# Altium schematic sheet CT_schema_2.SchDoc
size 271 x 273 mm
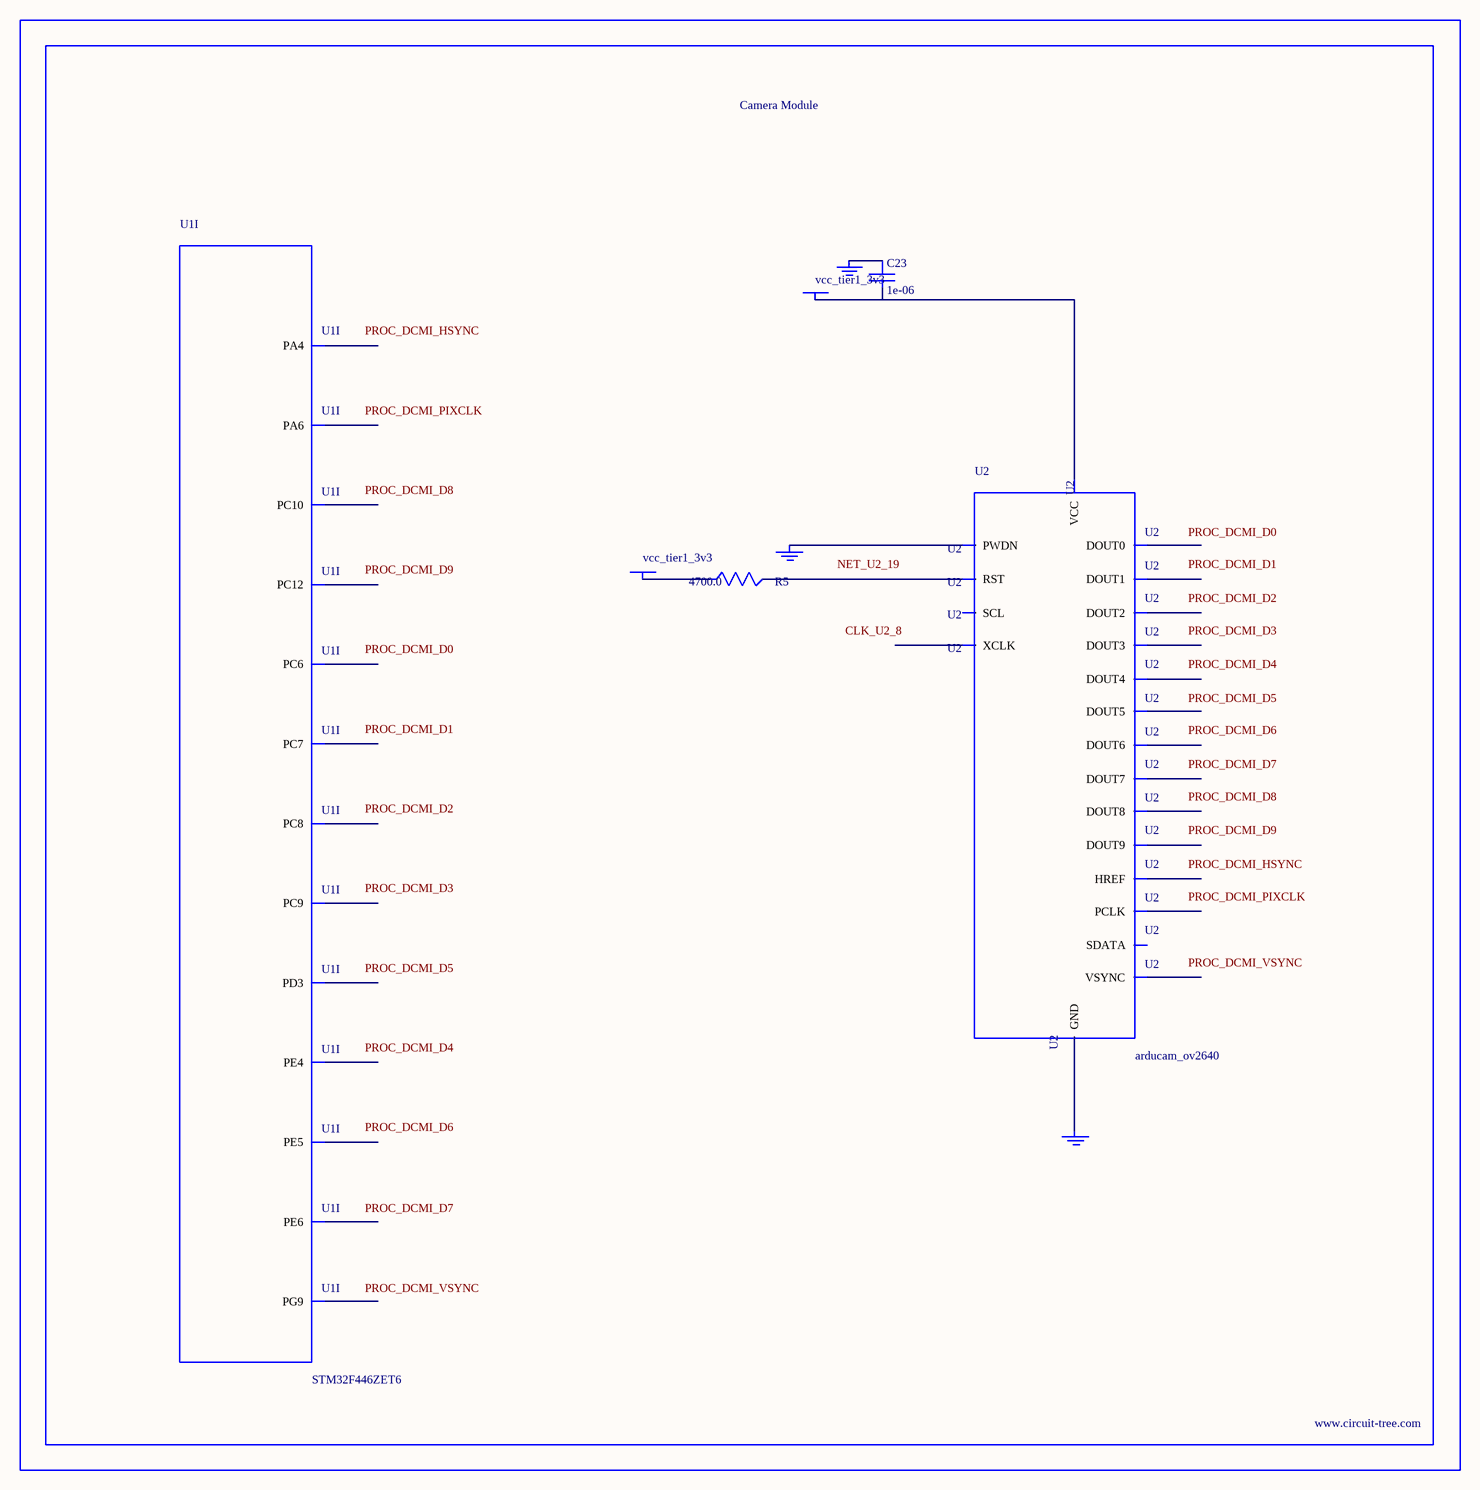
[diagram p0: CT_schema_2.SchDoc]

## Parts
BORDER1  (no value)
C23  1e-06  [C0603]
GND_INSTANCE_1_0  (no value)
GND_INSTANCE_1_1  (no value)
GND_INSTANCE_1_2  (no value)
POWER_INSTANCE_1_0  vcc_tier1_3v3
POWER_INSTANCE_1_1  vcc_tier1_3v3
R5  4700.0  [R0603]
U1  STM32F446ZET6  [LQFP144]  (part I of 11)
U2  arducam_ov2640  [ARDUCAM]

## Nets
NetC23_1: C23.1 GND_INSTANCE_1_0.0(GND)
NetC23_2: C23.2 POWER_INSTANCE_1_0.0(PWR) U2.1(VCC)
NetGND_INSTANCE_1_1_0: GND_INSTANCE_1_1.0(GND) U2.20(PWDN)
NetGND_INSTANCE_1_2_0: GND_INSTANCE_1_2.0(GND) U2.2(GND)
NetPOWER_INSTANCE_1_1_0: POWER_INSTANCE_1_1.0(PWR) R5.1
NetR5_2: R5.2 U2.19(RST)

Not connected (* = marked no-connect by the designer): U1 3(PE4) 4(PE5) 5(PE6) 40(PA4) 42(PA6) 96(PC6) 97(PC7) 98(PC8) 99(PC9) 111(PC10) 113(PC12) 117(PD3) 124(PG9); U2 3(SCL) 4(SDATA) 5(VSYNC) 6(HREF) 7(PCLK) 8(XCLK) 9(DOUT9) 10(DOUT8) 11(DOUT7) 12(DOUT6) 13(DOUT5) 14(DOUT4) 15(DOUT3) 16(DOUT2) 17(DOUT1) 18(DOUT0)

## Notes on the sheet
- Labels drawn without touching a wire or pin: CLK_U2_8, NET_U2_19, PROC_DCMI_D0, PROC_DCMI_D1, PROC_DCMI_D2, PROC_DCMI_D3, PROC_DCMI_D4, PROC_DCMI_D5, PROC_DCMI_D6, PROC_DCMI_D7, PROC_DCMI_D8, PROC_DCMI_D9, PROC_DCMI_HSYNC, PROC_DCMI_PIXCLK, PROC_DCMI_VSYNC

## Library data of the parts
BORDER1 = BORDER_PAGE1
C23 = C0603C105K3RACTU
GND_INSTANCE_1_0-GND_INSTANCE_1_2 = GND
POWER_INSTANCE_1_0 POWER_INSTANCE_1_1 = PWR
R5 = RC0603JR-074K7L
